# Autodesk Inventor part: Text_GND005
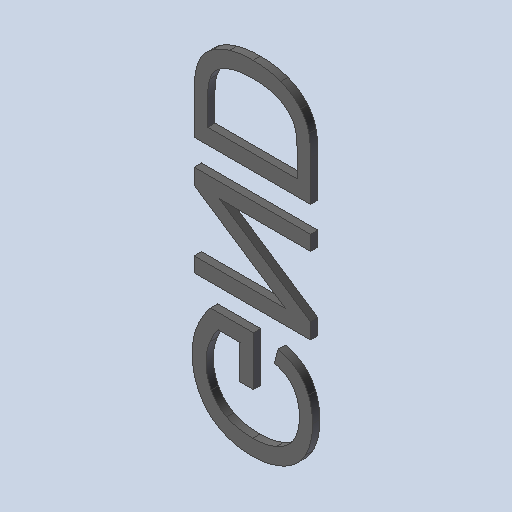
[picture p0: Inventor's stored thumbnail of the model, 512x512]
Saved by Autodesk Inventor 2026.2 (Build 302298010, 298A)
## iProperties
Created: 2026-10
Part Number: Text_GND005
Material: Générique
Document SubType Name: Modeling
Designer: mel
Density: 1 g/cm^3
Appearance: Par défaut
Author: mel
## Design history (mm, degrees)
feature "Base1"
feature "Base2"
feature "Base3"
node "Solide1"
node "Solide2"
node "Solide3"
